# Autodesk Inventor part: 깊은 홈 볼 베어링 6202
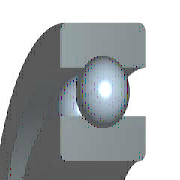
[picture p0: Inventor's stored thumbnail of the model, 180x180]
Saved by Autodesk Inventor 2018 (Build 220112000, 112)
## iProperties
IsCustomPart: 1
Created: 2012-02
Part Number: 깊은 홈 볼 베어링 6202
Material: 강철, 연강
Description: 깊은 그루부 볼 베어링
Document SubType Name: Modeling
Standard: JIS B 1521
Designer: mdu-01
Standards Organization: JIS
Language: ko-KR
Size Designation: 6202 15x35x11
Categories: <MemberInstance><Categories><Category DisplayName="샤프트 부품" InternalName="7f7aeb1f-a693-4053-b835-cee3144e0d98" Mnemonic="SHFT"><Category DisplayName="베어링" Inter
Density: 1 g/cm^3
Appearance: 강철(1)
Author: mdu-01
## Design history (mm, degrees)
sketch "스케치" dims "d0" = 5.2 (= -0.26 x WD + 0.26 x BD)
  geometry: L1 (2.9, 12.5)-(8.1, 12.5); L2 (5.5, 12.5)-(5.5, 9.9); L3 (5.5, 12.5)-(5.5, 15.1); L4 (3.568, 10.76)-(0, 10.76); L5 (0, 7.5)-(11, 7.5); L6 (3.568, 14.24)-(0, 14.24); L7 (0, 17.5)-(11, 17.5); L8 (11, 7.5)-(11, 10.76); L9 (7.432, 10.76)-(11, 10.76); L10 (7.432, 14.24)-(11, 14.24); L11 (11, 17.5)-(11, 14.24); L12 (-1.4, 0)-(8.4, 0) reference; L13 (0, -0.3)-(0, 5.3) reference
  constraints: 22 end point, 4 point on line, 2 collinear, 2 perpendicular, 2 symmetric about line, 1 midpoint, 1 parallel, 14 other
  dimensions: "d9" = 15 diameter of L5 L12 (= WD); "d11" = 35 diameter of L7 L12 (= BD); "d12" = 11 distance between parallel lines of L8 L13 (= KB); "d13" = 21.52 diameter of L9 L12 (= 0.326 x BD + 0.674 x WD)
revolve "본체" stored, may be unused: angle "d6" = 90 deg
revolve "볼" stored, may be unused: angle "d7" = 90 deg
pattern_circular "IDS_ARRAYBALL[SIMPL:T]" dims angle "d3" = 360 deg
body "Solid1"
fillet "모깎기1" dims "d1" = 0.6 (= KRS)
other parameters: "WD" = 15 [user parameter; used in 5 equation terms], "BD" = 35 [user parameter; used in 5 equation terms], "KB" = 11 [user parameter; used in 1 equation term], "KRS" = 0.6 [user parameter; used in 1 equation term], "d4" = 0, "d5" = 0, "d8" = 0, "d14" = 0, "d15" = 0, "BBA" = 0 [user parameter], "BC0" = 3750000 [user parameter], "BC" = 7800000 [user parameter], "BR" = 17.5 (= 0.5 x BD) [user parameter], "WR" = 7.5 (= 0.5 x WD) [user parameter]
